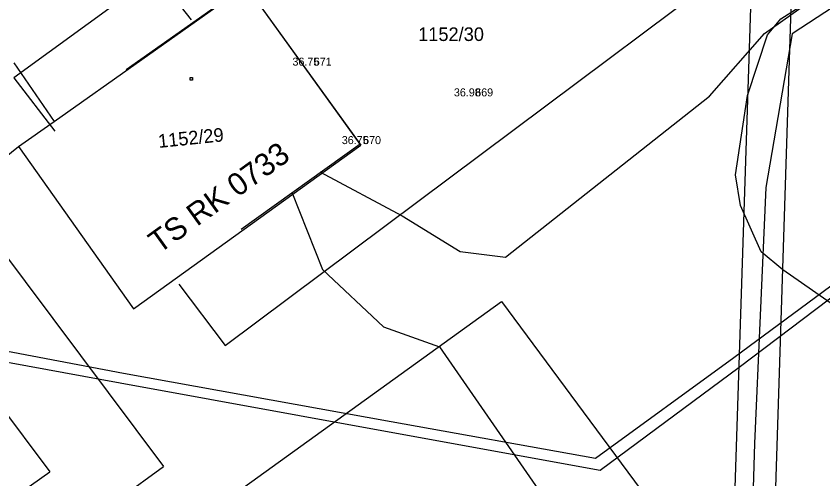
# Model space of a CAD drawing. Extents: x -609709 to -609357, y -1051535 to -1051131.
# Drawn here: x -609620.63 to -609595.44, y -1051331.13 to -1051316.68 of the extents above; entities that cross this region are included whole.
import ezdxf

# ---------------------------------------------------------------- set-up
doc = ezdxf.new("R2010")
doc.units = 0
for name, color, linetype in [('Vrstva 1', 7, 'Continuous'), ('Vrstva 10', 7, 'Continuous'), ('Vrstva 12', 7, 'Continuous'), ('Vrstva 15', 7, 'Continuous'), ('Vrstva 19', 7, 'Continuous'), ('Vrstva 2', 7, 'Continuous'), ('Vrstva 3', 7, 'Continuous'), ('Vrstva 9', 7, 'Continuous')]:
    doc.layers.add(name, color=color, linetype=linetype)

msp = doc.modelspace()

# ---------------------------------------------------------------- linework, layer by layer
at = {"layer": 'Vrstva 1'}
for p, q in [((-609611.43, -1051318.23), (-609611.43, -1051318.23)), ((-609606.39, -1051319.19), (-609606.39, -1051319.19)), ((-609609.89, -1051320.68), (-609609.89, -1051320.68))]:
    msp.add_line(p, q, dxfattribs=at)
at = {"layer": 'Vrstva 10'}
for p, q in [((-609598.65, -1051385.24), (-609596.25, -1051310.74)), ((-609599.55, -1051372.92), (-609597.54, -1051311.69)), ((-609619.44, -1051319.97), (-609613.46, -1051315.74)), ((-609613.46, -1051315.74), (-609609.87, -1051320.71)), ((-609620.7, -1051318.14), (-609619.44, -1051319.97)), ((-609615.195, -1051318.605), (-609615.12, -1051318.605)), ((-609615.195, -1051318.68), (-609615.195, -1051318.605)), ((-609615.12, -1051318.68), (-609615.195, -1051318.68)), ((-609615.12, -1051318.605), (-609615.12, -1051318.68)), ((-609620.56, -1051320.76), (-609619.44, -1051319.97)), ((-609616.97, -1051325.82), (-609609.87, -1051320.71)), ((-609622.4, -1051322.24), (-609620.56, -1051320.76)), ((-609620.56, -1051320.76), (-609616.97, -1051325.82)), ((-609622.4, -1051322.24), (-609616.03, -1051330.75)), ((-609624.19, -1051339.08), (-609605.48, -1051325.6)), ((-609605.48, -1051325.6), (-609598.35, -1051335.21)), ((-609622.01, -1051327.66), (-609619.58, -1051330.92)), ((-609625.28, -1051337.44), (-609616.03, -1051330.75)), ((-609623.99, -1051334.02), (-609619.58, -1051330.92))]:
    msp.add_line(p, q, dxfattribs=at)
at = {"layer": 'Vrstva 12'}
for points in [[(-609644.336, -1051251.436), (-609604.801, -1051307.048), (-609620.698, -1051318.606), (-609619.426, -1051320.272)], [(-609615.546, -1051325.052), (-609614.108, -1051326.974), (-609589.099, -1051308.266), (-609582.815, -1051303.565), (-609514.844, -1051393.856), (-609499.807, -1051382.785), (-609467.693, -1051377.467)], [(-609611.146, -1051321.543), (-609608.58, -1051322.92), (-609606.77, -1051324.03), (-609605.35, -1051324.21), (-609598.98, -1051319.18), (-609597.27, -1051317.23), (-609591.09, -1051312.83), (-609587.26, -1051310.28), (-609585.26, -1051309.71), (-609584.965, -1051309.999)], [(-609615.16, -1051316.797), (-609615.47, -1051316.4), (-609616.96, -1051313), (-609619.33, -1051311.61), (-609620.02, -1051310.61), (-609623.46, -1051313.37), (-609631.88, -1051319.51), (-609632.148, -1051319.084)], [(-609612.018, -1051322.176), (-609611.07, -1051324.6), (-609609.16, -1051326.39), (-609607.41, -1051327.01), (-609600.56, -1051336.92), (-609602.67, -1051340.83), (-609602.79, -1051350.77), (-609603.67, -1051357.26)]]:
    msp.add_lwpolyline(points, dxfattribs=at)
at = {"layer": 'Vrstva 15'}
for points in [[(-609588.82, -1051311.77), (-609594.6, -1051316.05), (-609596.4, -1051317.24), (-609597.23, -1051322.04), (-609597.58, -1051330.03), (-609597.74, -1051335.22)], [(-609591.07, -1051329.67), (-609593.09, -1051327.12), (-609596.69, -1051324.61), (-609597.37, -1051324.04), (-609598.02, -1051322.6), (-609598.17, -1051321.64), (-609597.8, -1051319.16), (-609597.17, -1051317.27), (-609596.76, -1051316.77), (-609594.67, -1051315.43), (-609593.9, -1051314.91), (-609591.92, -1051313.69), (-609590.24, -1051312.51), (-609590.03, -1051312.18), (-609589.59, -1051312.11), (-609588.92, -1051312.29), (-609588.35, -1051312.29), (-609588.06, -1051312.55)]]:
    msp.add_lwpolyline(points, dxfattribs=at)
at = {"layer": 'Vrstva 19'}
for points in [[(-609589.4, -1051320.8), (-609592.21, -1051322.91), (-609598.22, -1051327.36), (-609602.54, -1051330.5), (-609608.92, -1051329.35), (-609617.28, -1051327.84), (-609624.2, -1051326.53), (-609628.88, -1051319.66)], [(-609629.15, -1051319.84), (-609624.31, -1051326.87), (-609617.38, -1051328.14), (-609608.98, -1051329.67), (-609602.4, -1051330.86), (-609598.06, -1051327.65), (-609592.07, -1051323.12), (-609589.26, -1051320.99)]]:
    msp.add_lwpolyline(points, dxfattribs=at)
at = {"layer": 'Vrstva 9'}
for points in [[(-609609.89, -1051320.68), (-609613.46, -1051315.72), (-609617.194, -1051318.361)], [(-609609.89, -1051320.68), (-609613.602, -1051323.352)]]:
    msp.add_lwpolyline(points, dxfattribs=at)

# ---------------------------------------------------------------- texts
at = {"layer": 'Vrstva 10'}
msp.add_text('1152/30', height=0.425, dxfattribs=at).set_placement((-609608.08, -1051317.46))
msp.add_text('1152/29', height=0.425, rotation=5.8998, dxfattribs=at).set_placement((-609616.175, -1051320.801))
at = {"layer": 'Vrstva 12'}
msp.add_text('TS RK 0733', height=0.7, rotation=35.7433, dxfattribs=at).set_placement((-609616.167, -1051324.118))
at = {"layer": 'Vrstva 2'}
for s, p in [(' 671', (-609611.43, -1051318.23)), (' 669', (-609606.39, -1051319.19)), (' 670', (-609609.89, -1051320.68))]:
    msp.add_text(s, height=0.25, dxfattribs=at).set_placement(p)
at = {"layer": 'Vrstva 3'}
for s, p in [('36.75', (-609612.003, -1051318.23)), ('36.98', (-609606.963, -1051319.19)), ('36.75', (-609610.463, -1051320.68))]:
    msp.add_text(s, height=0.25, dxfattribs=at).set_placement(p)

doc.saveas('drawing.dxf')
